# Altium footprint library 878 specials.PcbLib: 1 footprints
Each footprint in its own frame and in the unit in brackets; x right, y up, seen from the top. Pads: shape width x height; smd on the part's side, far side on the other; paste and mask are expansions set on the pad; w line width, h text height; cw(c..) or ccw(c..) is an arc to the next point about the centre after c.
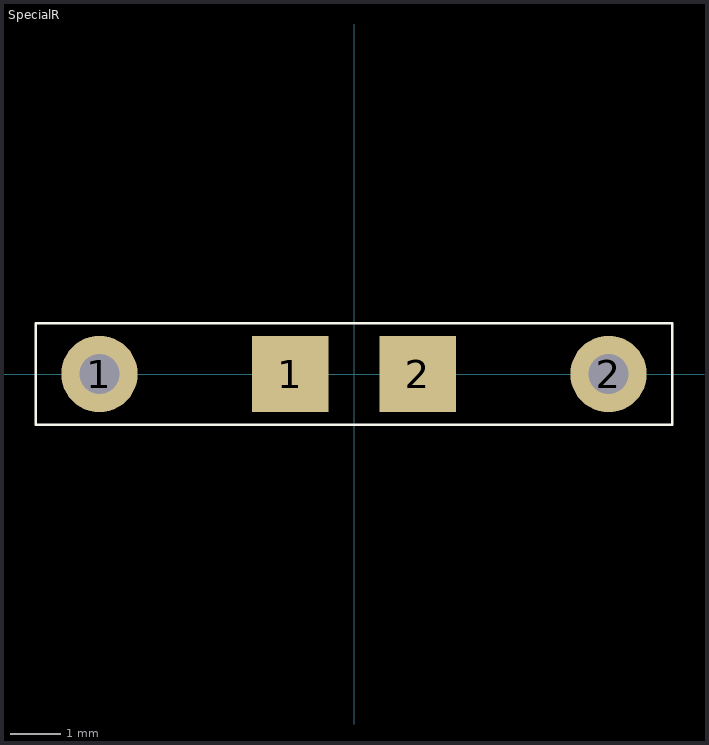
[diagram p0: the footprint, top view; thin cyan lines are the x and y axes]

## SpecialR [mil] "SM or TH"
pads (4):
  round 60 hole 31.5: 1(-200,0) 2(200,0)
  rect 60x60 smd: 1(-50,0) 2(50,0)
Top Overlay:
  lines w2: -250,-40 250,-40 250,40 -250,40 -250,-40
